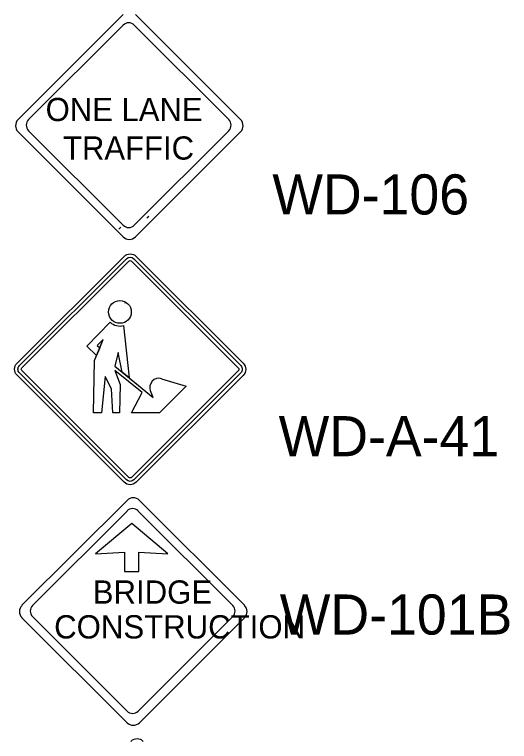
# Model space of a CAD drawing. Extents: x 2179 to 2395, y 134 to 413.
# Drawn here: x 2239.62 to 2265.41, y 178.24 to 216.14 of the extents above; entities that cross this region are included whole.
import ezdxf

# ---------------------------------------------------------------- set-up
doc = ezdxf.new("R2010")
doc.units = 0
for name, color, linetype in [('Level 1', 7, 'Continuous'), ('Level 10', 7, 'Continuous'), ('Level 2', 7, 'Continuous'), ('Level 44', 7, 'Continuous')]:
    doc.layers.add(name, color=color, linetype=linetype)

# ---------------------------------------------------------------- blocks, each defined once
blk = doc.blocks.new('2_95')
at = {"layer": 'Level 1'}
for points in [[(18.2, 120.1), (22.8, 116.1), (17.3, 102.4), (0, 118.7), (41.6, 161.7)], [(18.2, 120.1), (22.8, 116.1), (17.3, 102.4), (0, 118.7), (41.6, 161.7)], [(32.4, 65), (26.3, 0), (11.7, 0), (13.7, 93.4), (17.3, 102.4), (0, 118.7), (41.6, 161.7)], [(65.4, 155.5), (75.1, 62.6), (62.7, 72.8), (55.6, 107.5), (49.8, 83.3), (117.8, 27.3), (113.1, 39.4)], [(65.4, 155.5), (75.1, 62.6), (62.7, 72.8), (55.6, 107.5), (49.8, 83.3), (117.8, 27.3), (113.1, 39.4)], [(65.4, 155.5), (75.1, 62.5), (117.8, 27.3), (113.1, 39.4)], [(132.9, 60.9), (176.6, 47.8), (129.3, 0), (79.5, 0), (98.2, 36), (49.8, 75.6), (59.3, 50.4), (58.1, 0), (46.2, 0), (44, 43), (32.4, 65), (26.3, 0), (11.7, 0), (13.7, 93.4), (28.7, 130.9), (18.2, 120.1)], [(132.9, 60.9), (176.6, 47.8), (129.3, 0), (79.5, 0), (98.2, 36), (49.8, 75.6), (59.3, 50.4), (58.1, 0), (46.2, 0), (44, 43), (32.4, 65), (26.3, 0), (11.7, 0), (13.7, 93.4), (28.7, 130.9), (18.2, 120.1)], [(132.9, 60.9), (176.6, 47.8), (129.3, 0), (79.5, 0), (98.2, 36), (49.8, 75.6), (59.3, 50.4), (58.1, 0), (46.2, 0), (44, 43), (32.4, 65)]]:
    blk.add_lwpolyline(points, dxfattribs=at)
for points in [[(18.2, 120.1), (22.8, 116.1), (28.7, 130.9)], [(62.7, 72.8), (55.6, 107.5), (49.8, 83.3)]]:
    blk.add_lwpolyline(points, close=True, dxfattribs=at)
blk.add_circle((58.9, 179.8), 20.2, dxfattribs=at)
blk.add_circle((58.9, 179.8), 20.2, dxfattribs=at)
blk.add_circle((58.9, 179.8), 20.2, dxfattribs=at)
for centre, radius, start, end in [((58.9, 179.8), 25.1, 226.3135, 284.9576), ((58.9, 179.8), 25.1, 226.3135, 284.9576), ((58.9, 179.8), 25.1, 226.3135, 284.9576), ((128.2, 45.3), 16.3, 73.381, 201.0999), ((128.2, 45.3), 16.3, 73.381, 201.0999), ((128.2, 45.3), 16.3, 73.381, 201.0999)]:
    blk.add_arc(centre, radius, start, end, dxfattribs=at)
blk = doc.blocks.new('WDA41')
at = {"layer": 'Level 1'}
for p, q in [((-6.546, 0.348), (-0.352, 6.542)), ((-6.408, 0.211), (-0.215, 6.404)), ((0.21, 6.405), (6.408, 0.214)), ((0.348, 6.543), (6.545, 0.352)), ((-6.271, 0.073), (-0.077, 6.267)), ((0.072, 6.267), (6.27, 0.077)), ((0.287, 3.829), (0.303, 3.829)), ((-0.348, -6.542), (-6.546, -0.352)), ((-0.211, -6.404), (-6.408, -0.214)), ((-0.073, -6.266), (-6.27, -0.076)), ((6.27, -0.072), (0.076, -6.266)), ((6.408, -0.209), (0.214, -6.404)), ((6.546, -0.348), (0.352, -6.542))]:
    blk.add_line(p, q, dxfattribs=at)
for centre, radius, start, end in [((-0.002, 6.192), 0.495, 45.0349, 135), ((-0.002, 6.192), 0.3, 45.0349, 135), ((-0.002, 6.192), 0.105, 45.0349, 135), ((-6.196, -0.002), 0.495, 135, 225.0349), ((-6.196, -0.002), 0.3, 135, 225.0349), ((-6.196, -0.002), 0.105, 135, 225.0349), ((6.195, 0.002), 0.105, 315, 45.035), ((6.195, 0.002), 0.3, 315, 45.035), ((6.195, 0.002), 0.495, 315, 45.035), ((0.002, -6.192), 0.105, 225.0348, 315), ((0.002, -6.192), 0.495, 225.0348, 315), ((0.002, -6.192), 0.3, 225.0348, 315)]:
    blk.add_arc(centre, radius, start, end, dxfattribs=at)
at = {"layer": 'Level 1', "xscale": 0.032498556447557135, "yscale": -0.032498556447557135, "rotation": 180}
blk.add_blockref('2_95', (2.502, -2.524), dxfattribs=at)

msp = doc.modelspace()

# ---------------------------------------------------------------- linework, layer by layer
at = {"layer": 'Level 2'}
for p, q in [((2246.616, 205.622), (2246.513, 205.518)), ((2245.162, 205.057), (2245.059, 204.953))]:
    msp.add_line(p, q, dxfattribs=at)
at = {"layer": 'Level 44'}
for p, q in [((2245.278, 216.144), (2239.8, 210.675)), ((2251.395, 210.675), (2245.926, 216.144)), ((2240.349, 210.67), (2245.278, 215.592)), ((2245.861, 215.592), (2250.784, 210.67)), ((2239.8, 210.025), (2245.278, 204.55)), ((2239.805, 210.025), (2239.8, 210.025)), ((2245.278, 205.159), (2240.349, 210.085)), ((2250.784, 210.085), (2245.861, 205.159)), ((2245.926, 204.55), (2251.395, 210.025)), ((2245.482, 190.809), (2240.004, 185.34)), ((2251.599, 185.34), (2246.13, 190.809)), ((2240.553, 185.335), (2245.482, 190.258)), ((2246.065, 190.258), (2250.988, 185.335)), ((2245.724, 189.612), (2243.841, 188.026)), ((2247.605, 188.026), (2245.724, 189.612)), ((2243.841, 188.026), (2245.346, 188.107)), ((2245.346, 188.107), (2245.346, 187.102)), ((2246.101, 187.102), (2246.101, 188.107)), ((2246.101, 188.107), (2247.605, 188.026)), ((2245.346, 187.102), (2246.096, 187.102)), ((2240.004, 184.69), (2245.482, 179.215)), ((2240.009, 184.69), (2240.004, 184.69)), ((2245.482, 179.824), (2240.553, 184.751)), ((2250.988, 184.751), (2246.065, 179.824)), ((2246.13, 179.215), (2251.599, 184.69))]:
    msp.add_line(p, q, dxfattribs=at)
for centre, radius, start, end in [((2245.568, 215.302), 0.412, 45, 135), ((2240.128, 210.349), 0.458, 135, 225), ((2240.643, 210.377), 0.412, 135, 225), ((2250.493, 210.377), 0.412, 315, 45), ((2251.073, 210.349), 0.458, 315, 45), ((2245.568, 205.451), 0.412, 225, 315), ((2245.601, 204.876), 0.458, 225, 315), ((2245.805, 190.488), 0.458, 45, 135), ((2245.772, 189.968), 0.412, 45, 135), ((2240.332, 185.015), 0.458, 135, 225), ((2240.847, 185.043), 0.412, 135, 225), ((2250.697, 185.043), 0.412, 315, 45), ((2251.277, 185.015), 0.458, 315, 45), ((2245.772, 180.117), 0.412, 225, 315), ((2245.805, 179.542), 0.458, 225, 315), ((2246.002, 177.918), 0.458, 45, 135)]:
    msp.add_arc(centre, radius, start, end, dxfattribs=at)

# ---------------------------------------------------------------- block references
at = {"layer": 'Level 1', "xscale": 0.9, "yscale": -0.9, "rotation": 180}
msp.add_blockref('WDA41', (2245.641, 197.647), dxfattribs=at)

# ---------------------------------------------------------------- texts
at = {"layer": 'Level 10'}
for s, height, p in [('ONE LANE', 1.2095, (2241.239, 210.588)), ('TRAFFIC', 1.2095, (2242.144, 208.58)), ('WD-106', 2.09, (2253.052, 205.719)), ('WD-A-41', 2.09, (2253.382, 193.114)), ('WD-101B', 2.09, (2253.441, 183.815))]:
    msp.add_text(s, height=height, dxfattribs=at).set_placement(p)
at = {"layer": 'Level 44'}
for s, height, p in [('BRIDGE', 1.214, (2243.693, 185.425)), ('CONSTRUCTION', 1.21397, (2241.683, 183.611))]:
    msp.add_text(s, height=height, rotation=360, dxfattribs=at).set_placement(p)

doc.saveas('drawing.dxf')
